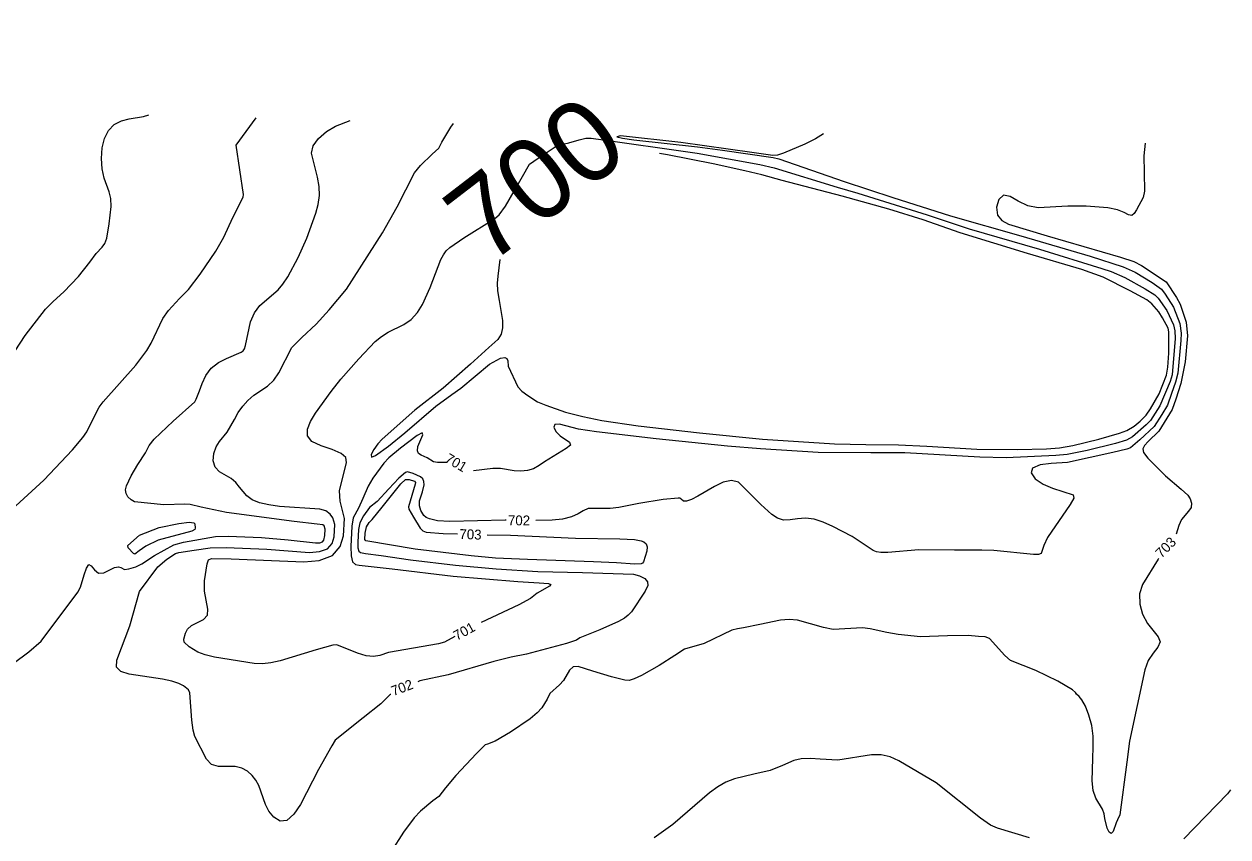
# Model space of a CAD drawing. Extents: x -291892836 to 2945206, y -477993085 to 1832792.
# Drawn here: x 1849014 to 1849499.5, y 545001.4 to 545329.4 of the extents above; entities that cross this region are included whole.
import ezdxf

# ---------------------------------------------------------------- set-up
doc = ezdxf.new("R2010")
doc.units = 0
for name, color, linetype in [('DT_X_Contour_Minor', 7, 'Continuous'), ('DT_X_Terrain_Ground_Line', 7, 'Continuous'), ('Level 19', 7, 'Continuous')]:
    doc.layers.add(name, color=color, linetype=linetype)

msp = doc.modelspace()

# ---------------------------------------------------------------- linework, layer by layer
at = {"layer": 'DT_X_Contour_Minor'}
for points in [[(1849022.01, 545145.33), (1849033.52, 545157.56), (1849037.75, 545162.49), (1849039.32, 545164.84), (1849041.53, 545169.25), (1849044.38, 545174.73), (1849045.96, 545176.9), (1849059.11, 545191.74), (1849063.58, 545197.67), (1849065.24, 545200.57), (1849070.03, 545210.55), (1849072.29, 545213.76), (1849076.65, 545218.64), (1849080.29, 545222.23), (1849084.98, 545228.49), (1849091.4, 545237.75), (1849094.57, 545243.45), (1849098.28, 545251.33), (1849102.43, 545259.49), (1849102.56, 545260.62), (1849099.56, 545280.49), (1849107.58, 545291.54)], [(1849050.42, 545288.91), (1849053.26, 545290.37), (1849056.36, 545291.15), (1849062.14, 545292.09), (1849064.38, 545292.76)], [(1849010.41, 545197.58), (1849014.49, 545203.78), (1849022.61, 545214.31), (1849025.72, 545217.42), (1849030.06, 545221.32), (1849036.02, 545227.58), (1849040.56, 545233.24), (1849043.08, 545236.75), (1849045.59, 545239.31), (1849046.64, 545240.9), (1849047.37, 545243.02), (1849048.32, 545248.79), (1849049.1, 545255.79), (1849049, 545259.01), (1849048.33, 545261.71), (1849046.3, 545267.24), (1849045.55, 545270.96), (1849045.25, 545275.15), (1849045.52, 545279.39), (1849046.49, 545283.26), (1849048.13, 545286.5), (1849050.42, 545288.91)], [(1849161.87, 545058.91), (1849161.71, 545058.79), (1849157.89, 545055.12), (1849150.72, 545049.37), (1849139.53, 545040.47), (1849138.17, 545038.07), (1849132.74, 545028.58), (1849125.45, 545014.46), (1849122.82, 545010.53), (1849120.02, 545008.03), (1849117.25, 545007.79), (1849114.74, 545009.31), (1849112.74, 545011.76), (1849111.41, 545014.44), (1849108.76, 545022.08), (1849107.55, 545024.26), (1849106.04, 545026.2), (1849104.18, 545027.88), (1849101.9, 545029.13), (1849099.11, 545029.76), (1849092.47, 545029.74), (1849089.58, 545030.56), (1849087.54, 545032.73), (1849082.95, 545041.84), (1849082.17, 545044.41), (1849081.72, 545048.47), (1849080.88, 545059.52), (1849080.32, 545060.73), (1849078.26, 545062.34), (1849076.41, 545063.33), (1849073.64, 545064.28), (1849069.79, 545065.1), (1849056.35, 545067.09), (1849053.07, 545068.11), (1849051.33, 545069.86), (1849051.46, 545072.66), (1849056.7, 545086.58), (1849060.55, 545100.36), (1849067.99, 545110.37), (1849071.64, 545113.4), (1849075.07, 545115.69), (1849076.43, 545116.17), (1849082.64, 545117.15), (1849089.02, 545118.1), (1849095.48, 545118.2), (1849111.96, 545117.5), (1849129.2, 545116.2), (1849133.2, 545116.51), (1849136.4, 545117.66), (1849138.24, 545119.82), (1849139.02, 545122.44), (1849139.34, 545127.49), (1849138.55, 545130.09), (1849137.51, 545131.68), (1849135.77, 545132.95), (1849133.25, 545133.59), (1849116.99, 545134.76), (1849112.78, 545135.36), (1849108.91, 545136.24), (1849106.01, 545137.46), (1849103.93, 545138.97), (1849100.95, 545142.55), (1849099.46, 545144.37), (1849097.6, 545145.98), (1849092.85, 545148.72), (1849091.06, 545150.59), (1849090.35, 545153.19), (1849090.59, 545156.12), (1849091.5, 545158.84), (1849092.83, 545160.96), (1849095.95, 545164.7), (1849098.84, 545169.85), (1849100.4, 545172.62), (1849102.21, 545175.2), (1849104.31, 545177.52), (1849106.73, 545179.58), (1849112.2, 545183.32), (1849114.71, 545185.67), (1849116.76, 545188.65), (1849122.05, 545198.85), (1849126.09, 545202.84), (1849131.84, 545208.22), (1849137.1, 545214.11), (1849144.02, 545222.45), (1849158.62, 545245.11), (1849164.45, 545255.65), (1849171.45, 545269.41), (1849173.88, 545272.36), (1849178.62, 545276.89), (1849181.28, 545279.26), (1849182.5, 545281.76), (1849186.08, 545287.75), (1849187.19, 545289.28)], [(1849101.63, 545196.98), (1849102.38, 545197.58), (1849102.92, 545198.38), (1849103.38, 545199.7), (1849105.39, 545209.19), (1849106.92, 545212.88), (1849109.15, 545215.79), (1849116.51, 545222.13), (1849118.44, 545224.49), (1849120.37, 545227.45), (1849124.6, 545235.22), (1849128.11, 545242.94), (1849131.74, 545253.03), (1849132.67, 545256.54), (1849133.14, 545260.17), (1849133, 545263.9), (1849132.37, 545267.58), (1849129.97, 545277.24), (1849130.61, 545280.21), (1849132.77, 545283.23), (1849135.98, 545286.01), (1849139.57, 545288.2), (1849145.52, 545290.46)], [(1849187.73, 545082.29), (1849183.57, 545079.99), (1849181.14, 545079.34), (1849161, 545075.8), (1849157.44, 545074.61), (1849155, 545074.22), (1849151.99, 545074.44), (1849148.43, 545075.48), (1849140.17, 545078.85), (1849138.55, 545078.82), (1849131.86, 545076.87), (1849117.24, 545072.47), (1849113.59, 545071.6), (1849110.23, 545071.22), (1849106.83, 545071.38), (1849090.79, 545073.97), (1849087.04, 545074.84), (1849084.17, 545075.93), (1849080.62, 545078.14), (1849078.53, 545080.01), (1849078.48, 545081.2), (1849079.14, 545083.64), (1849079.97, 545085.25), (1849081.53, 545086.73), (1849086.38, 545089.1), (1849088.01, 545090.8), (1849088.18, 545093.35), (1849086.78, 545100.54), (1849086.77, 545104.69), (1849087.87, 545111.56), (1849088.39, 545113.21), (1849089.59, 545113.79), (1849097.5, 545113.56), (1849126.85, 545112.35), (1849133.1, 545112.95), (1849138.41, 545114.9), (1849141.52, 545118.53), (1849142.84, 545122.88), (1849143.31, 545129.91), (1849141.56, 545136.83), (1849141.23, 545141.1), (1849144.02, 545152.43), (1849143.76, 545154.44), (1849141.96, 545156.15), (1849138.26, 545157.66), (1849133.8, 545159.18), (1849130.09, 545160.97), (1849128.33, 545163.21), (1849128.34, 545165.91), (1849129.6, 545169.02), (1849131.62, 545172.43), (1849137.81, 545181.12), (1849141.83, 545186.15), (1849148.97, 545194.29), (1849155.6, 545201.23), (1849158.17, 545203.37), (1849160.83, 545205.01), (1849167.12, 545208.09), (1849170.16, 545210.19), (1849172.71, 545213), (1849174.76, 545216.29), (1849177.79, 545223.05), (1849182.1, 545234.32), (1849183.14, 545236.33), (1849184.22, 545237.88), (1849185.7, 545239.28), (1849191.33, 545243.12), (1849203.84, 545250.96), (1849205.56, 545252.45), (1849208.2, 545255.94), (1849211.65, 545262), (1849217.79, 545272.87), (1849221.29, 545275.3), (1849229.01, 545280.41), (1849233.7, 545281.5), (1849237.85, 545282.61), (1849240.54, 545283.35), (1849242.67, 545283.37), (1849253.4, 545281.8), (1849276.12, 545278.61), (1849285.43, 545277.26), (1849310.81, 545272.67), (1849316.52, 545271.37), (1849341.92, 545263.55), (1849350.32, 545261.19), (1849378.24, 545252.42), (1849395.16, 545246.8), (1849423.51, 545238.51), (1849448.62, 545230.78), (1849452.41, 545229.52), (1849457.97, 545227.07), (1849466.19, 545222.59), (1849470, 545220.09), (1849471.37, 545218.78), (1849474.84, 545213.86), (1849477.57, 545207.96), (1849478.08, 545205.55), (1849478.21, 545202.56), (1849476.98, 545187.84), (1849476.25, 545185.19), (1849472.04, 545175.35)], [(1849336.39, 545285.06), (1849336.38, 545285.05), (1849333.25, 545283.04), (1849328.87, 545280.89), (1849320.24, 545277.33), (1849317.89, 545276.5), (1849315.97, 545276.35), (1849307.53, 545277.54), (1849278.88, 545281.57), (1849254.55, 545284.31), (1849253.05, 545283.94), (1849255.42, 545283.35), (1849259.93, 545282.7), (1849285.55, 545279.84), (1849295.71, 545278.53), (1849316.09, 545275.59), (1849318.4, 545275.02), (1849344.73, 545265.9), (1849364.42, 545259.41), (1849387.62, 545252), (1849416.04, 545243.96), (1849443.99, 545235.66), (1849457.21, 545231.41), (1849462.06, 545229.21), (1849468.96, 545225.06), (1849472.66, 545222.44), (1849474.21, 545220.33), (1849477.52, 545215.14), (1849480.12, 545208.55), (1849480.65, 545204.6), (1849480.57, 545201.74), (1849479.26, 545188.5), (1849478.43, 545184.92), (1849476.74, 545180.28), (1849475.08, 545175.66), (1849472.91, 545171.9), (1849469.79, 545167.05), (1849464.04, 545161.6), (1849460.25, 545158.37), (1849458.69, 545157.81), (1849453.14, 545156.45), (1849434.81, 545152.47), (1849428.27, 545152.08), (1849423.82, 545151.47), (1849420.69, 545150.24), (1849420.15, 545148.26), (1849421.83, 545145.92), (1849424.94, 545143.74), (1849428.73, 545142.12), (1849437.14, 545139.4), (1849437.31, 545138.09), (1849435.89, 545135.57), (1849426.78, 545122.19), (1849425.3, 545118.94), (1849424.21, 545115.77), (1849423.11, 545115.34), (1849421.11, 545115.4), (1849405.1, 545116.99), (1849400.27, 545117.1), (1849389.22, 545117.07), (1849374.93, 545117.17), (1849362.33, 545116.17), (1849359.55, 545116.17), (1849357.78, 545116.45), (1849356.5, 545117.01), (1849348.03, 545122.57), (1849340.23, 545126.69), (1849336.31, 545128.38), (1849332.6, 545129.54), (1849329.13, 545130.02), (1849325.94, 545129.77), (1849323.01, 545129.29), (1849320.33, 545129.21), (1849317.86, 545130), (1849315.54, 545131.52), (1849311.09, 545135.58), (1849302.09, 545144.49), (1849299.29, 545145.27), (1849296, 545144.51), (1849292.44, 545142.72), (1849285.79, 545138.83), (1849283.17, 545137.55), (1849281.21, 545136.88), (1849280, 545136.85), (1849279.02, 545137.71), (1849278.68, 545138.03), (1849277.76, 545138.12), (1849271.78, 545137.5), (1849262.01, 545135.99), (1849253.86, 545134.31), (1849250.38, 545133.89), (1849241.49, 545133.93), (1849239.45, 545133.03), (1849237.43, 545131.73), (1849234.81, 545130.48), (1849231.18, 545129.66), (1849226.97, 545129.23), (1849220.4, 545129.06)], [(1849205.84, 545234.35), (1849205.15, 545227.59), (1849204.76, 545224.89), (1849204.93, 545221.78), (1849205.57, 545217.83), (1849206.94, 545209.74), (1849206.98, 545206.86), (1849206.42, 545204.26), (1849205.11, 545202.14), (1849201.5, 545198.91), (1849194.03, 545192.18), (1849182.98, 545182.51), (1849171.65, 545173.55), (1849158.39, 545161.84), (1849156.72, 545159.95), (1849155.11, 545157.67), (1849154.02, 545155.63), (1849154.09, 545154.65), (1849155.7, 545155.29), (1849160.97, 545159.04), (1849167.54, 545164.4), (1849180.15, 545175.19), (1849186.6, 545179.88), (1849190.15, 545182.49), (1849201.74, 545192.21), (1849206.18, 545194.54), (1849207.87, 545194.9), (1849208.78, 545194.45), (1849209.1, 545193.5), (1849209.27, 545191.35), (1849213.15, 545183.04), (1849214.81, 545181.19), (1849217.13, 545179.44), (1849221.14, 545177), (1849224.42, 545175.57), (1849232.38, 545172.84), (1849239.3, 545171.01), (1849247.09, 545169.48), (1849261.68, 545167.22), (1849286.48, 545164.43), (1849311.81, 545161.84), (1849340.87, 545160.03), (1849353.55, 545159.79), (1849366.67, 545159.6), (1849378.07, 545159.07), (1849398.22, 545157.87), (1849414.7, 545157.65), (1849426.4, 545157.99), (1849431.62, 545158.45), (1849436.96, 545159.39), (1849447.43, 545161.9), (1849455.74, 545164.24), (1849458.76, 545165.42), (1849461.74, 545167.11), (1849464.16, 545169.18), (1849466.48, 545171.55), (1849468.34, 545174.12), (1849471.79, 545180.15), (1849474.8, 545187.76), (1849475.34, 545191), (1849475.64, 545196.58), (1849475.66, 545205.17), (1849475.35, 545206.66), (1849473.14, 545210.86), (1849471.66, 545213.23), (1849468.8, 545216.51), (1849466.75, 545218.07), (1849460.15, 545221.69), (1849449.24, 545227.2), (1849440.63, 545230.35), (1849418.66, 545236.74), (1849391.56, 545245.1), (1849376.55, 545250.43), (1849362.71, 545254.65), (1849343.88, 545259.98), (1849319.74, 545266.23), (1849311.55, 545268.55), (1849304.64, 545270.12), (1849291.86, 545272.92), (1849273.56, 545276.62), (1849270.29, 545277.12)], [(1849466.13, 545281.38), (1849465.56, 545276.16), (1849465.76, 545269.52), (1849465.93, 545261.92), (1849465.39, 545259.42), (1849462.65, 545254.4), (1849461.75, 545252.89), (1849460.74, 545252.1), (1849459.48, 545252.39), (1849457.65, 545253.38), (1849454.92, 545254.49), (1849451.1, 545255.28), (1849442.33, 545255.96), (1849434.98, 545255.95), (1849422.98, 545255.19), (1849418.79, 545255.98), (1849414.99, 545257.86), (1849411.7, 545259.78), (1849409.02, 545260.35), (1849407.08, 545258.65), (1849406.15, 545255.54), (1849406.55, 545252.33), (1849408.4, 545250.06), (1849411, 545248.69), (1849426.65, 545243.99), (1849456.22, 545235.26), (1849461.56, 545233.64), (1849464.72, 545231.95), (1849474.59, 545225.4), (1849478.78, 545219.07), (1849480.21, 545216.42), (1849482.67, 545209.13), (1849483.16, 545203.61), (1849482.25, 545193.11), (1849480.48, 545184.32), (1849478.51, 545178.03), (1849477.01, 545173.84), (1849471.7, 545165.1), (1849467.37, 545160.89), (1849465.92, 545159.27), (1849465.16, 545157.94), (1849465.45, 545156.46), (1849467.16, 545154.21), (1849474.35, 545147.04), (1849480.59, 545141.67), (1849483.37, 545139.25), (1849484.28, 545137.78), (1849484.8, 545136.05), (1849484.64, 545134.35), (1849483.65, 545132.82), (1849480.79, 545129.43), (1849479.78, 545127.1), (1849478.63, 545123.59)], [(1849009.58, 545071.36), (1849015.98, 545076.08), (1849020.95, 545080.33), (1849035.77, 545100.2), (1849036.84, 545102.13), (1849038.31, 545107.1), (1849039.17, 545109.85), (1849040.11, 545111.31), (1849041.15, 545110.74), (1849042.42, 545109.11), (1849044.09, 545107.85), (1849046.21, 545108), (1849050.54, 545110.05), (1849052.06, 545110.35), (1849053.08, 545110.1), (1849054.52, 545109.27), (1849056.29, 545109.54), (1849059.13, 545110.38), (1849061.53, 545111.61), (1849066.61, 545114.89), (1849074.38, 545119.28), (1849078.39, 545120.29), (1849091.27, 545122.65), (1849096.34, 545122.79), (1849109.77, 545122.2), (1849120.53, 545121.29), (1849131.54, 545120.05), (1849133.31, 545120.07), (1849134.38, 545120.42), (1849134.95, 545121.1), (1849135.32, 545122.99), (1849135.47, 545125.57), (1849135.02, 545126.86), (1849134.48, 545127.27), (1849132.21, 545127.61), (1849122.9, 545128.71), (1849095.61, 545132.27), (1849085.39, 545134.51), (1849081, 545135.46), (1849078.8, 545135.61), (1849070.37, 545135.34), (1849058.53, 545136.63), (1849057.17, 545137.42), (1849055.94, 545138.61), (1849055.14, 545140.01), (1849054.95, 545141.46), (1849055.33, 545143.06), (1849057.25, 545147.13), (1849059.86, 545151.66), (1849062.97, 545156.4), (1849064.51, 545159.39), (1849066.51, 545161.86), (1849074.09, 545169.21), (1849082.83, 545177.01), (1849083.49, 545178), (1849084.84, 545181.45), (1849085.84, 545184.33), (1849087.33, 545187.57), (1849089.51, 545190.57), (1849092.45, 545192.86), (1849095.65, 545194.47), (1849101.63, 545196.98)], [(1849472.04, 545175.35), (1849468.29, 545169.48), (1849466.49, 545167.64), (1849461.09, 545162.82), (1849458.64, 545161.52), (1849454.14, 545160.14), (1849442.7, 545157.37), (1849434.63, 545155.63), (1849430.13, 545155.24), (1849410.12, 545154.35), (1849399.53, 545154.65), (1849369.17, 545156.39), (1849355.46, 545156.4), (1849334.3, 545156.5), (1849311.05, 545157.99), (1849297.77, 545159.08), (1849268.92, 545162), (1849244.93, 545164.86), (1849237.65, 545165.96), (1849229.99, 545167.94), (1849228.14, 545167.81), (1849227.71, 545166.71), (1849228.54, 545165.01), (1849230.24, 545163.26), (1849234.04, 545160.72), (1849234.36, 545159.52), (1849232.7, 545158.06), (1849223.93, 545152.8), (1849221.69, 545151.19), (1849219.49, 545149.94), (1849217.02, 545149.18), (1849214.35, 545148.91), (1849211.62, 545149.06), (1849206.12, 545150.01), (1849203.09, 545150.1), (1849195.22, 545149.05)], [(1849184.33, 545152.42), (1849180.7, 545152.46), (1849179.14, 545152.79), (1849176.53, 545154.41), (1849174.11, 545155.38), (1849173.13, 545156.1), (1849172.63, 545157.23), (1849172.87, 545158.99), (1849174.84, 545163.58), (1849174.63, 545164.47), (1849172.51, 545163.36), (1849165.84, 545158.3), (1849161.1, 545154.36), (1849159.1, 545152.21), (1849154.65, 545146.13), (1849152.77, 545142.98), (1849150.58, 545137.99), (1849148.84, 545133.99), (1849146.7, 545130.13), (1849146.25, 545126.81), (1849145.75, 545118.62), (1849145.88, 545114.77), (1849146.54, 545112.44), (1849147.67, 545111.37), (1849149.19, 545110.99), (1849162.47, 545109.6), (1849187.13, 545106.65), (1849213.16, 545104.46), (1849221.78, 545103.93), (1849225.58, 545103.69), (1849226.5, 545103.29), (1849225.86, 545102.59), (1849220.94, 545099.69), (1849218.31, 545097.63), (1849213.59, 545095.09), (1849198.3, 545087.97)], [(1849208.4, 545129.14), (1849208.02, 545129.15), (1849185.73, 545128.7), (1849180.71, 545128.98), (1849177.47, 545129.67), (1849176.25, 545130.28), (1849175.3, 545131.11), (1849174.07, 545133.11), (1849173.44, 545135.04), (1849173.48, 545136.97), (1849174.64, 545140.62), (1849175.35, 545143.48), (1849175.3, 545144.74), (1849174.85, 545145.83), (1849173.92, 545146.75), (1849170.9, 545148.07), (1849168.59, 545148.68), (1849167.83, 545148.48), (1849165.14, 545146.12), (1849161.07, 545141.85), (1849156.48, 545136.71), (1849153.36, 545134.3), (1849150.94, 545130.92), (1849149.4, 545128.06), (1849148.93, 545125.39), (1849148.6, 545120.38), (1849148.67, 545118.1), (1849149.06, 545116.72), (1849149.73, 545116.09), (1849151.73, 545115.75), (1849158.09, 545114.95), (1849169.86, 545113.19), (1849188.05, 545111.04), (1849204.35, 545109.55), (1849221.24, 545108.52), (1849239.18, 545108.04), (1849259.86, 545107.39), (1849262.22, 545106.8), (1849264.32, 545105.64), (1849265.43, 545104.3), (1849265.58, 545102.89), (1849264.45, 545100.53), (1849258.97, 545092.26), (1849257.66, 545090.82), (1849256.22, 545089.71), (1849253.77, 545088.31), (1849246.17, 545084.98), (1849238.16, 545081.65), (1849236.77, 545080.78), (1849232.8, 545079.42), (1849216.7, 545075.06), (1849210.4, 545073.98), (1849203.41, 545072.16), (1849185.04, 545066.8), (1849173.61, 545064.33), (1849172.77, 545064.02)], [(1849005.86, 545130.53), (1849022.01, 545145.33)], [(1849200.82, 545123.29), (1849210.14, 545123.13), (1849236.43, 545121.96), (1849254.24, 545121.63), (1849260.18, 545121.46), (1849262.89, 545120.91), (1849263.99, 545120.39), (1849264.9, 545119.59), (1849265.36, 545118.38), (1849265.22, 545116.73), (1849263.8, 545112.44), (1849263.46, 545111.91), (1849262.88, 545111.64), (1849260.33, 545111.47), (1849252.95, 545111.94), (1849243.64, 545112.39), (1849217.03, 545113.3), (1849204.09, 545113.9), (1849194.38, 545114.82), (1849171.73, 545117.47), (1849151.79, 545120.81), (1849151.47, 545121.42), (1849151.6, 545123.98), (1849152.15, 545126.45), (1849153.24, 545128.31), (1849154.38, 545129.46), (1849158.44, 545134.44), (1849165.97, 545143.91), (1849167.91, 545145.59), (1849169.36, 545145.66), (1849171.5, 545144.97), (1849171.86, 545144.44), (1849171.79, 545143.7), (1849169.04, 545134.58), (1849169.2, 545133.68), (1849171.03, 545130.38), (1849173.76, 545126.01), (1849174.81, 545124.83), (1849176.22, 545124.3), (1849183.02, 545123.82), (1849188.83, 545123.63)], [(1849055.84, 545118.99), (1849060.52, 545123.18), (1849068.47, 545126.27), (1849076.39, 545127.82), (1849080.62, 545128.36), (1849082.43, 545128.16), (1849082.91, 545127.67), (1849083.04, 545126.03), (1849082.83, 545125.46), (1849081.75, 545124.81), (1849068.17, 545121.16), (1849063.08, 545118.76), (1849060.46, 545116.87), (1849058.68, 545115.45), (1849058.14, 545115.72), (1849055.95, 545117.97), (1849055.84, 545118.99)], [(1849471.53, 545113.73), (1849471.35, 545113.47), (1849465.04, 545103.28), (1849463.89, 545099.44), (1849463.96, 545095.32), (1849465.11, 545091.22), (1849467.04, 545087.54), (1849471.36, 545082.16), (1849472.19, 545080.04), (1849471.31, 545077.93), (1849469.39, 545075.56), (1849467.38, 545072.61), (1849465.99, 545068.86), (1849459.83, 545040.01), (1849458.75, 545031.51), (1849455.99, 545010.35), (1849454.98, 545008.23), (1849454.41, 545007.12), (1849453.19, 545003.62), (1849452.46, 545002.7), (1849451.64, 545003.24), (1849450.84, 545004.85), (1849449.9, 545008.86), (1849449.57, 545010.73), (1849448.91, 545012.62), (1849446.3, 545017.08), (1849445.19, 545020.14), (1849444.73, 545023.98), (1849445.01, 545033.01), (1849445.21, 545037.57), (1849445.14, 545042.03), (1849444.6, 545046.38), (1849443.47, 545050.55), (1849442.02, 545054.16), (1849440.63, 545056.75), (1849439.58, 545058.05), (1849438.5, 545058.93), (1849438.09, 545059.63), (1849436.8, 545060.77), (1849430.9, 545064.2), (1849422.11, 545068.51), (1849411.87, 545072.62), (1849409.52, 545074.64), (1849403.34, 545081.42), (1849401.6, 545082.09), (1849398.93, 545082.29), (1849394.75, 545082.61), (1849386.38, 545082.46), (1849375.49, 545082.16), (1849366.55, 545083.1), (1849361.92, 545083.86), (1849355.27, 545085.41), (1849352.19, 545085.73), (1849340.34, 545085.12), (1849336.36, 545085.82), (1849325.91, 545088.8), (1849322.64, 545089.06), (1849319.04, 545088.8), (1849310.77, 545087.09), (1849304.12, 545085.79), (1849301.75, 545085.41), (1849299.47, 545084.75), (1849288.26, 545079.46), (1849280.42, 545077.08), (1849276.46, 545074.64), (1849270.11, 545070.53), (1849263.01, 545066.52), (1849260.12, 545065.18), (1849258.03, 545064.55), (1849256.24, 545064.57), (1849250.88, 545065.96), (1849243.46, 545068.29), (1849237.53, 545070.15), (1849235.46, 545069.97), (1849233.96, 545068.64), (1849231.51, 545064.46), (1849230.02, 545062.72), (1849226.01, 545059.26), (1849224.95, 545056.92), (1849222.78, 545053.47), (1849220.93, 545051.41), (1849218.15, 545049.02), (1849210.18, 545043.61), (1849204.01, 545040.01), (1849200.93, 545038.75), (1849200.01, 545038.52), (1849196.48, 545034.99), (1849188.18, 545026.2), (1849183.93, 545021.2), (1849181.26, 545017.71), (1849178.81, 545015.99), (1849173.96, 545011.78), (1849171.31, 545009.03), (1849167.05, 545003.36), (1849162.1, 544995.5)], [(1849419.48, 545001.01), (1849406.57, 545004.87), (1849403.73, 545006.19), (1849399.77, 545008.99), (1849381.82, 545023.25), (1849366.76, 545032.11), (1849363.28, 545033.68), (1849359.61, 545034.54), (1849355.74, 545034.48), (1849342.21, 545032.37), (1849335.14, 545032.73), (1849331.15, 545032.96), (1849327.48, 545032.87), (1849324.51, 545032.26), (1849319.84, 545030.16), (1849314.91, 545028.2), (1849308.27, 545026.68), (1849300.59, 545024.88), (1849297.08, 545023.45), (1849293.79, 545021.56), (1849290.5, 545019.15), (1849275.66, 545006.36), (1849268.12, 545000.99)], [(1849500.55, 545020.38), (1849499.34, 545018.78), (1849481.73, 545000.61)]]:
    msp.add_lwpolyline(points, dxfattribs=at)

# ---------------------------------------------------------------- texts
at = {"layer": 'DT_X_Terrain_Ground_Line'}
for s, p in [('24336GB04.PRF', (1846112.16, 544943.17)), ('ROT=43.3446', (1847031.35, 544779.43))]:
    msp.add_text(s, height=500, rotation=43.3446, dxfattribs=at).set_placement(p)
at = {"layer": 'Level 19'}
for s, height, rotation, p in [('700', 33, 37.5574, (1849200.94, 545231.48)), ('701', 4, 329.233, (1849183.42, 545152.96)), ('702', 4, 359.4279, (1849209.15, 545127.14)), ('703', 4, 358.1502, (1849189.54, 545121.61)), ('703', 4, 45.2694, (1849472.7, 545113.65)), ('701', 4, 28.9516, (1849188.58, 545080.47)), ('702', 4, 20.7296, (1849162.98, 545058.17))]:
    msp.add_text(s, height=height, rotation=rotation, dxfattribs=at).set_placement(p)

doc.saveas('drawing.dxf')
